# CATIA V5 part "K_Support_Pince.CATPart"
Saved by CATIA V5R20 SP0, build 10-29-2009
Part number: Support_Pince
Publications: "Distance_Inter_Pivot", "Epaisseur_Cloison", "Encombrement_Lame", "Epaisseur_Branche", "Epaisseur_Cloison.1", "Distance_Inter_Pivot.1", "Rayon_Pivot", "Encombrement_Lame.1", "Corps principal", "Plan_Réf_Support", "Droite.1", "Centre_Pivot_Support2", "Centre_Pivot_Support1", "Point.3", "Point.4", "Point.5", "Point.6", "Droite.2", "Droite.3", "Plan_Capot1", "Plan.3"
Bounding box of the stored display mesh (mm): x -30.5 to 30.5, y -30 to 230, z -30 to 97.685
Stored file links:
  G:\Khaled_CFAO_2011\SIL\SIL_GR1\mneves\Khaled\CAD_CATIA_Modifie\K_Support_Pince.CATPart
  G:\Khaled_CFAO_2011\SIL\SIL_GR1\mneves\Khaled\CAD_CATIA_Modifie\K_AssPince_A_Bois.CATProduct
  G:\Khaled_CFAO_2011\SIL\SIL_GR1\mneves\Khaled\CAD_CATIA\Branche1.CATPart
  G:\Khaled_CFAO_2011\SIL\SIL_GR1\mneves\Khaled\CAD_CATIA\Branche2.CATPart
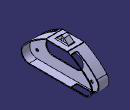
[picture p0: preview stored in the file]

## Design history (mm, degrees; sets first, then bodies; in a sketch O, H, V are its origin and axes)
External parameters (linked from other documents)
  External.Distance_Inter_Pivot = 200 mm
  External.Epaisseur_Cloison = 3 mm
  External.Encombrement_Lame = 12 mm
  External.Epaisseur_Branche = 15 mm
  External.Epaisseur_Cloison.1 = 3 mm
  External.Rayon_Pivot = 5 mm
  External.Distance_Inter_Pivot.1 = 200 mm
  External.Encombrement_Lame.1 = 12 mm
  `External.Epaisseur_Vérin` = 6 mm
  External.Epaisseur_Branche.1 = 15 mm
Set1
  Plane1 "Plan_Réf_Support": linked copy from another document
  Line1: linked copy from another document
  Point1 "Centre_Pivot_Support2": linked copy from another document
  Point2 "Centre_Pivot_Support1": linked copy from another document
  Point3 to Point6: linked copy from another document
  Line2: linked copy from another document
  Line3: linked copy from another document
  Plane2 "Plan_Capot1": linked copy from another document
  Plane3: linked copy from another document
Body1 (main body)
  Sketch1 on Plane1, origin (0, 0, 0), H (0, 1, 0), V (0, 0, 1)
    line L1 (0, -30) -> (200, -30)
    reference projected line E1 (0, 0) -> (200, 0) from Line1
    arc A1 centre (200, 0) radius 30 from (200, -30) to (222.2183, 20.158) ccw
    point P3 (200, 0)
    reference projected point E2 (200, 0) from Point1
    arc A2 centre (0, 0) radius 30 from (-22.2183, 20.158) to (0, -30) ccw
    point P4 (0, 0)
    reference projected point E3 (0, 0) from Point2
    line L2 (60, 80) -> (140, 80)
    point P5 (60, 80)
    point P6 (140, 80)
    reference projected line E4 (0, 0) -> (200, 0) from Line1
    arc A3 centre (37.0658, -147.8257) radius 250 from (222.2183, 20.158) to (140, 80) ccw
    point P9 (60, 80)
    arc A4 centre (162.9342, -147.8257) radius 250 from (-22.2183, 20.158) to (60, 80) cw
    construction line L3 (56.7401, 35) -> (143.2599, 35)
    point P12 (56.7401, 35)
    point P13 (143.2599, 35)
    line L4 (56.7401, 60) -> (143.2599, 60)
    line L5 (143.2599, 10) -> (56.7401, 10)
    arc A5 centre (143.2599, 35) radius 25 from (143.2599, 60) to (143.2599, 10) cw
    arc A6 centre (56.7401, 35) radius 25 from (56.7401, 10) to (56.7401, 60) cw
    reference projected line E5 (0, 0) -> (200, 0) from Line1
    reference projected point E6 (0, 0) from Point2
    reference projected point E7 (200, 0) from Point1
    reference projected point E8 (0, 0) from Point2
    reference projected point E9 (200, 0) from Point1
    circle A7 centre (0, 0) radius 5
    point P18 (0, 0)
    circle A8 centre (200, 0) radius 5
    point P19 (200, 0)
    reference projected point E10 (200, 0) from Point1
    reference projected point E11 (0, 0) from Point2
    distance E1 L1 = 30 {= External.Distance_Inter_Pivot.1  /8+External.Distance_Inter_Pivot.1 /40}
    distance E4 L2 = 80 {= External.Distance_Inter_Pivot.1 /2.5}
    radius A3 = 250 {= External.Distance_Inter_Pivot.1  *5/4}
    radius A4 = 250 {= External.Distance_Inter_Pivot.1  *5/4}
    distance E5 L5 = 10 {= External.Distance_Inter_Pivot /20}
    radius A6 = 25 {= External.Distance_Inter_Pivot.1 /8}
    distance E6 P12 = 66.6667 {= External.Distance_Inter_Pivot.1 /3}
    distance P13 E7 = 66.6667 {= External.Distance_Inter_Pivot.1 /3}
    distance E8 P5 = 100 {= External.Distance_Inter_Pivot.1 /2}
    distance E9 P6 = 100 {= External.Distance_Inter_Pivot.1  /2}
    radius A8 = 5 {= External.Distance_Inter_Pivot.1 /40}
    radius A7 = 5 {= External.Distance_Inter_Pivot.1  /40}
    coincidence: E2 P3, E3 P4, P9 P5, P19 E10, E11 P18
    tangency: L1 A1, A3 A1, A4 A2, A5 L4, A6 L4, A5 L5, A6 L5, L1 A2
    horizontal: L2 H, L3 H
    parallelism: L3 L4
  Pad1: profile Sketch1, direction (1, 0, 0), length 30.5 {= External.Epaisseur_Cloison /2+External.Encombrement_Lame +External.Epaisseur_Branche +2mm}, mirrored extent
  Sketch2 on end face of Pad1, origin (30.5, 0, 0), H (0, 1, 0), V (0, 0, 1)
    line L1 (0, -27) -> (200, -27)
    point P1 (0, -27)
    reference projected line E1 (0, -30) -> (200, -30) from edge [face of Pad1 from Sketch1.L1 | end face of Pad1]
    arc A1 centre (0, 0) radius 27 from (-20.0921, 18.0363) to (0, -27) ccw
    point P3 (0, 0)
    arc A2 centre (200, 0) radius 27 from (200, -27) to (220.0921, 18.0363) ccw
    point P4 (200, 0)
    reference projected point E2 (0, 0) from Point2
    reference projected point E3 (200, 0) from Point1
    line L2 (58.9915, 77) -> (141.0085, 77)
    point P5 (58.9915, 77)
    point P6 (141.0085, 77)
    reference projected line E4 (140, 80) -> (60, 80) from edge [face of Pad1 from Sketch1.L2 | end face of Pad1]
    arc A3 centre (34.0541, -148.9663) radius 250 from (220.0921, 18.0363) to (141.0085, 77) ccw
    point P9 (58.9915, 77)
    arc A4 centre (165.9459, -148.9663) radius 250 from (-20.0921, 18.0363) to (58.9915, 77) cw
    reference projected point E5 (0, 0) from Point2
    reference projected point E6 (200, 0) from Point1
    distance L1 E1 = 3 {= External.Epaisseur_Cloison.1}
    distance L2 E4 = 3 {= External.Epaisseur_Cloison.1}
    distance E5 P5 = 97 {= External.Distance_Inter_Pivot.1 /2-External.Epaisseur_Cloison.1}
    distance E6 P6 = 97 {= External.Distance_Inter_Pivot.1 /2-External.Epaisseur_Cloison.1}
    radius A4 = 250 {= External.Distance_Inter_Pivot.1 *5/4}
    radius A3 = 250 {= External.Distance_Inter_Pivot.1 *5/4}
    coincidence: P1 V, E2 P3, P4 E3, P9 P5
    horizontal: L1 H, L2 H
    tangency: L1 A2, L1 A1, A3 A2, A4 A1
  Pocket1: profile Sketch2, direction (-1, 0, 0), length 29 {= 2mm+External.Epaisseur_Branche +External.Encombrement_Lame}
  Sketch3 on start face of Pad1, origin (-30.5, 0, 0), H (0, -1, 0), V (0, 0, 1)
    line L1 (-200, -27) -> (0, -27)
    point P1 (0, -27)
    reference projected line E1 (0, -30) -> (-200, -30) from edge [start face of Pad1 | face of Pad1 from Sketch1.L1]
    arc A1 centre (0, 0) radius 27 from (0, -27) to (20.0921, 18.0363) ccw
    point P3 (0, 0)
    arc A2 centre (-200, 0) radius 27 from (-220.0921, 18.0363) to (-200, -27) ccw
    point P4 (-200, 0)
    reference projected point E2 (0, 0) from Point2
    reference projected point E3 (-200, 0) from Point1
    line L2 (-141.0085, 77) -> (-58.9915, 77)
    point P5 (-141.0085, 77)
    point P6 (-58.9915, 77)
    reference projected line E4 (-140, 80) -> (-60, 80) from edge [start face of Pad1 | face of Pad1 from Sketch1.L2]
    arc A3 centre (-165.9459, -148.9663) radius 250 from (20.0921, 18.0363) to (-58.9915, 77) ccw
    point P9 (-220.0921, 18.0363)
    reference projected point E5 (-200, 0) from Point1
    reference projected point E6 (0, 0) from Point2
    point P10 (-141.0085, 77)
    point P11 (-220.0921, 18.0363)
    arc A4 centre (-34.0541, -148.9663) radius 250 from (-220.0921, 18.0363) to (-141.0085, 77) cw
    distance E1 L1 = 3 {= External.Epaisseur_Cloison.1}
    distance L2 E4 = 3 {= External.Epaisseur_Cloison.1}
    distance E5 P5 = 97 {= External.Distance_Inter_Pivot.1 /2-External.Epaisseur_Cloison.1}
    distance E6 P6 = 97 {= External.Distance_Inter_Pivot.1 /2-External.Epaisseur_Cloison.1}
    radius A3 = 250 {= External.Distance_Inter_Pivot.1 *5/4}
    radius A4 = 250 {= External.Distance_Inter_Pivot.1 *5/4}
    coincidence: P1 V, E2 P3, P4 E3, P11 P9, P10 P5
    horizontal: L1 H, L2 H
    tangency: A1 L1, A2 L1, A1 A3, A2 A4
  Pocket2: profile Sketch3, direction (1, 0, 0), length 29 {= 2mm+External.Epaisseur_Branche +External.Encombrement_Lame}
  Sketch4 on face of Pad1 from Sketch1.L2, origin (0, 0, 80), H (1, 0, 0), V (0, 1, 0)
    line L1 (29, 150) -> (6, 150)
    line L2 (6, 230) -> (29, 230)
    line L3 (29, 230) -> (29, 150)
    point P3 (6, 230)
    reference projected line E1 (30.5, 222.2183) -> (30.5, 140) from edge [face of Pad1 from Sketch1.A3 | end face of Pad1]
    reference projected line E2 (-30.5, 200) -> (30.5, 200) from Line2
    point P5 (6, 230)
    point P6 (6, 230)
    line L4 (6, 150) -> (6, 230)
    point P7 (6, 230)
    distance E1 L3 = 1.5
    distance L1 L2 = 80 {= External.Distance_Inter_Pivot /2.5}
    distance E2 L2 = 30 {= External.Distance_Inter_Pivot.1 /8+External.Distance_Inter_Pivot.1 /40}
    distance L4 L3 = 23 {= External.Distance_Inter_Pivot.1 /100+External.Epaisseur_Branche.1 +`External.Epaisseur_Vérin`}
    horizontal: L1 H, L2 H
    vertical: L3 V, L4 V
    coincidence: P5 L2, P5 P3, P6 L2, P6 P3, P3 P7
  Pocket3: profile Sketch4, direction (0, 0, -1), length 133.3333 {= External.Distance_Inter_Pivot /1.5}
  Sketch5 on face of Pad1 from Sketch1.L2, origin (0, 0, 80), H (1, 0, 0), V (0, 1, 0)
    line L1 (-29, -30) -> (-29, 50)
    line L2 (-29, 50) -> (-13, 50)
    point P1 (-29, -30)
    reference projected line E1 (-30.5, 60) -> (-30.5, -22.2183) from edge [start face of Pad1 | face of Pad1 from Sketch1.A4]
    point P4 (-13, -30)
    line L3 (-13, -30) -> (-29, -30)
    point P5 (-29, -30)
    reference projected point E2 (0, 0) from Point2
    line L4 (-13, -30) -> (-13, 50)
    point P6 (-13, -30)
    distance E1 L1 = 1.5
    distance E2 L3 = 30 {= External.Distance_Inter_Pivot.1 /8+External.Distance_Inter_Pivot.1 /40}
    distance L2 L3 = 80 {= External.Distance_Inter_Pivot.1 /2.5}
    distance L4 L1 = 16 {= External.Distance_Inter_Pivot.1 /200+External.Epaisseur_Branche.1}
    horizontal: L2 H, L3 H
    vertical: L1 V
    coincidence: P5 P1, P4 P6
  Pocket4: profile Sketch5, direction (0, 0, -1), length 133.3333 {= External.Distance_Inter_Pivot /1.5}
  Sketch6 on face of Pocket2 from Sketch3.L1, origin (0, 0, -27), H (1, 0, 0), V (0, 1, 0)
    circle A1 centre (-7.5, 193) radius 3
    point P1 (-7.5, 193)
    circle A2 centre (-7.5, 7) radius 3
    point P2 (-7.5, 7)
    reference projected point E1 (-7.5, 193) from Point5
    reference projected point E2 (-7.5, 7) from Point6
    radius A1 = 3 {= External.Encombrement_Lame.1 /4}
    radius A2 = 3 {= External.Encombrement_Lame.1 /4}
    coincidence: P1 E1, P2 E2
  Pocket5: profile Sketch6, direction (0, 0, -1), length 4 {= External.Epaisseur_Cloison +1mm}
  Sketch7 on face of Pocket2 from Sketch3.L1, origin (0, 0, -27), H (1, 0, 0), V (0, 1, 0)
    arc A1 centre (-7.5, 7) radius 5 from (-12.5, 7) to (-2.5, 7) ccw
    point P1 (-7.5, 7)
    arc A2 centre (-7.5, 193) radius 3 from (-4.5, 193) to (-10.5, 193) ccw
    point P2 (-7.5, 193)
    arc A3 centre (-7.5, 193) radius 5 from (-2.5, 193) to (-12.5, 193) ccw
    point P3 (-7.5, 193)
    line L1 (-2.5, 193) -> (-4.5, 193)
    arc A4 centre (-7.5, 7) radius 3 from (-10.5, 7) to (-4.5, 7) ccw
    point P8 (-7.5, 7)
    line L2 (-2.5, 7) -> (-4.5, 7)
    line L3 (-10.5, 193) -> (-12.5, 193)
    line L4 (-10.5, 7) -> (-12.5, 7)
    reference projected line E1 (-30.5, 200) -> (30.5, 200) from Line2
    reference projected line E2 (-30.5, 0) -> (30.5, 0) from Line3
    reference projected point E3 (-7.5, 193) from Point5
    reference projected point E4 (-7.5, 193) from Point5
    reference projected point E5 (-7.5, 7) from Point6
    reference projected point E6 (-7.5, 7) from Point6
    radius A2 = 3 {= External.Encombrement_Lame.1  /4}
    radius A1 = 5 {= External.Encombrement_Lame.1  /4+2mm}
    radius A3 = 5 {= External.Encombrement_Lame.1  /4+2mm}
    radius A4 = 3 {= External.Encombrement_Lame.1 /4}
    distance L3 L1 = 0
    distance L1 E1 = 7 {= External.Distance_Inter_Pivot.1 /40+2mm}
    distance L4 L2 = 0
    distance L2 E2 = 7 {= External.Distance_Inter_Pivot.1 /40 +2mm}
    coincidence: P2 E3, E4 P3, P8 E5, P1 E6
  Pad2: profile Sketch7, direction (0, 0, 1), length 12 {= (External.Distance_Inter_Pivot.1 /8+External.Distance_Inter_Pivot.1 /40)/2-External.Epaisseur_Cloison.1}
  Sketch8 on Plane1, origin (0, 0, 0), H (0, 1, 0), V (0, 0, 1)
    arc A1 centre (100, 87.6853) radius 10 from (106.6238, 95.177) to (93.3762, 95.177) ccw
    point P1 (100, 87.6853)
    line L1 (106.6238, 95.177) -> (123.7894, 80)
    point P2 (106.6238, 95.177)
    point P3 (123.7894, 80)
    point P4 (76.2106, 80)
    point P5 (93.3762, 95.177)
    line L2 (93.3762, 95.177) -> (76.2106, 80)
    reference projected line E1 (140, 80) -> (60, 80) from edge [face of Pad1 from Sketch1.L2 | end face of Pad1]
    reference projected line E2 (140, 80) -> (60, 80) from edge [face of Pad1 from Sketch1.L2 | end face of Pad1]
    circle A2 centre (100, 87.6853) radius 5
    point P6 (100, 87.6853)
    line L3 (123.7894, 80) -> (76.2106, 80)
    point P7 (123.7894, 80)
    point P8 (76.2106, 80)
    reference projected point E3 (0, 0) from Point2
    reference projected point E4 (200, 0) from Point1
    radius A1 = 10 {= External.Distance_Inter_Pivot.1 /20}
    radius A2 = 5 {= External.Distance_Inter_Pivot.1  /40}
    distance P6 P4 = 25 {= External.Distance_Inter_Pivot.1 /8}
    distance P3 P6 = 25 {= External.Distance_Inter_Pivot.1 /8}
    distance P5 E3 = 133.3333 {= External.Distance_Inter_Pivot.1 /1.5}
    distance P2 E4 = 133.3333 {= External.Distance_Inter_Pivot.1 /1.5}
    tangency: L1 A1, L2 A1
    coincidence: P3 E1, P4 E2, P6 P1, P8 P4, P3 P7
    horizontal: L3 H
  Pad3: profile Sketch8, direction (1, 0, 0), length 10 {= External.Distance_Inter_Pivot /20}, mirrored extent
  Fillet1: radius 3, on edge [start face of Pad3 | face of Pad1 from Sketch1.L2]; edge [face of Pad1 from Sketch1.L2 | face of Pad3 from Sketch8.L2]; edge [face of Pad3 from Sketch8.L1 | face of Pad1 from Sketch1.L2]; edge [face of Pad1 from Sketch1.L2 | end face of Pad3]
  Fillet2: radius 1, on edge [face of Pocket2 from Sketch3.L1 | face of Pad2 from Sketch7.L1]; edge [face of Pad2 from Sketch7.L1 | end face of Pad2]; edge [face of Pad2 from Sketch7.L3 | end face of Pad2]; edge [face of Pocket2 from Sketch3.L1 | face of Pad2 from Sketch7.L3]; edge [face of Pad2 from Sketch7.L4 | end face of Pad2]; edge [face of Pad2 from Sketch7.L2 | end face of Pad2]; edge [face of Pocket2 from Sketch3.L1 | face of Pad2 from Sketch7.L2]; edge [face of Pocket2 from Sketch3.L1 | face of Pad2 from Sketch7.L4]
  Sketch9 on face of Pocket2 from Sketch3.L1, origin (0, 0, -27), H (1, 0, 0), V (0, 1, 0)
    line L1 (-9, 193) -> (-6, 193)
    line L2 (-6, 193) -> (-6, 7)
    line L3 (-6, 7) -> (-9, 7)
    line L4 (-9, 7) -> (-9, 193)
    reference projected point E1 (-7.5, 193) from Point5
    reference projected point E2 (-7.5, 7) from Point6
    reference projected point E3 (-7.5, 193) from Point5
    reference projected point E4 (-7.5, 193) from Point5
    distance E1 L1 = 0
    distance L3 E2 = 0
    distance E3 L4 = 1.5 {= External.Encombrement_Lame /8}
    distance L2 E4 = 1.5 {= External.Encombrement_Lame /8}
    horizontal: L1 H, L3 H
    vertical: L2 V, L4 V
  Pocket6: profile Sketch9, direction (0, 0, -1), length 5 {= External.Epaisseur_Cloison +2mm}
  Fillet3: radius 3, on edge [face of Pocket3 from Sketch4.L1 | face of Pocket3 from Sketch4.L4] (x2); edge [face of Pocket3 from Sketch4.L3 | face of Pocket3 from Sketch4.L1] (x2); edge [face of Pocket4 from Sketch5.L2 | face of Pocket4 from Sketch5.L4] (x2); edge [face of Pocket4 from Sketch5.L1 | face of Pocket4 from Sketch5.L2] (x2)
  Fillet4: radius 5, on edge [face of Pocket1 from Sketch2.L2 | face of Pocket1 from Sketch2.A3]; edge [face of Pocket1 from Sketch2.A4 | face of Pocket1 from Sketch2.L2]; edge [face of Pad1 from Sketch1.L2 | face of Pad1 from Sketch1.A3]; edge [face of Pad1 from Sketch1.A4 | face of Pad1 from Sketch1.L2]; edge [face of Pocket2 from Sketch3.L2 | face of Pocket2 from Sketch3.A3]; edge [face of Pocket2 from Sketch3.A4 | face of Pocket2 from Sketch3.L2]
